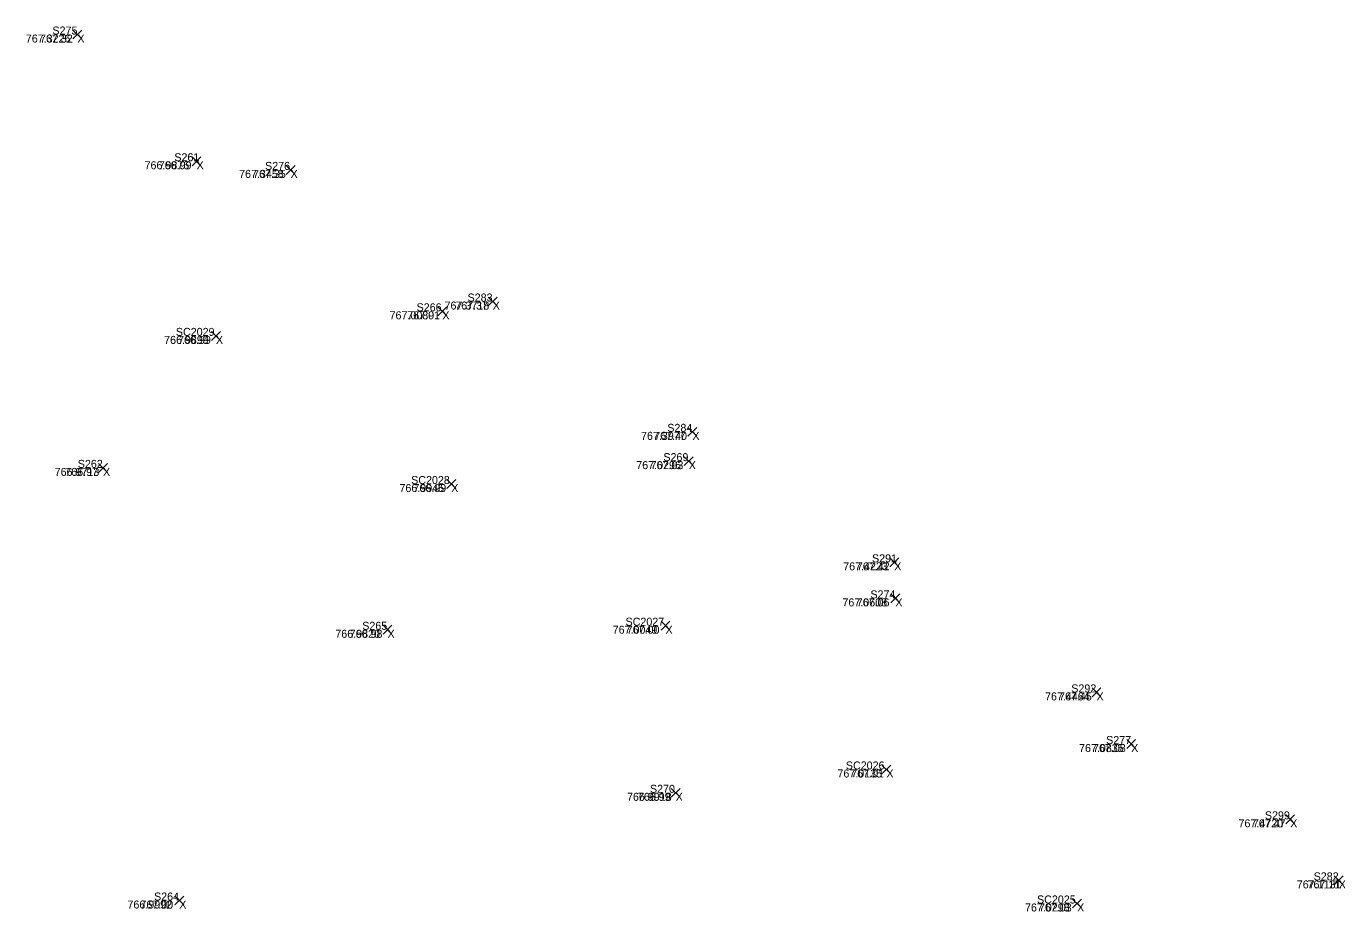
# Model space of a CAD drawing. Extents: x 1845019 to 1877956, y 680444 to 701081.
# Drawn here: x 1857647.67 to 1857657.56, y 694303.02 to 694309.65 of the extents above; entities that cross this region are included whole.
import ezdxf

# ---------------------------------------------------------------- set-up
doc = ezdxf.new("R2010")
doc.units = 0
for name, color, linetype in [('SV_X_Random_Point', 7, 'Continuous'), ('SV_X_Text_Comment', 7, 'Continuous'), ('SV_X_Text_Elevation', 7, 'Continuous'), ('SV_X_Text_Name', 7, 'Continuous')]:
    doc.layers.add(name, color=color, linetype=linetype)

msp = doc.modelspace()

# ---------------------------------------------------------------- linework, layer by layer
at = {"layer": 'SV_X_Random_Point'}
for p, q in [((1857648.0198, 694309.5546), (1857648.0864, 694309.6214)), ((1857648.0198, 694309.6214), (1857648.0864, 694309.5546)), ((1857648.0198, 694309.5546), (1857648.0864, 694309.6214)), ((1857648.0198, 694309.6214), (1857648.0864, 694309.5546)), ((1857648.9129, 694308.6049), (1857648.9795, 694308.6717)), ((1857648.9129, 694308.6717), (1857648.9795, 694308.6049)), ((1857648.9129, 694308.6049), (1857648.9795, 694308.6717)), ((1857648.9129, 694308.6717), (1857648.9795, 694308.6049)), ((1857649.6178, 694308.5401), (1857649.6844, 694308.6069)), ((1857649.6178, 694308.6069), (1857649.6844, 694308.5401)), ((1857649.6178, 694308.5401), (1857649.6844, 694308.6069)), ((1857649.6178, 694308.6069), (1857649.6844, 694308.5401)), ((1857651.1333, 694307.5537), (1857651.1999, 694307.6205)), ((1857651.1333, 694307.6205), (1857651.1999, 694307.5537)), ((1857651.1333, 694307.5537), (1857651.1999, 694307.6205)), ((1857651.1333, 694307.6205), (1857651.1999, 694307.5537)), ((1857650.7559, 694307.4806), (1857650.8225, 694307.5474)), ((1857650.7559, 694307.5474), (1857650.8225, 694307.4806)), ((1857650.7559, 694307.4806), (1857650.8225, 694307.5474)), ((1857650.7559, 694307.5474), (1857650.8225, 694307.4806)), ((1857649.0582, 694307.2962), (1857649.1248, 694307.363)), ((1857649.0582, 694307.363), (1857649.1248, 694307.2962)), ((1857649.0582, 694307.2962), (1857649.1248, 694307.363)), ((1857649.0582, 694307.363), (1857649.1248, 694307.2962)), ((1857652.6304, 694306.5771), (1857652.697, 694306.6439)), ((1857652.6304, 694306.6439), (1857652.697, 694306.5771)), ((1857652.6304, 694306.5771), (1857652.697, 694306.6439)), ((1857652.6304, 694306.6439), (1857652.697, 694306.5771)), ((1857652.603, 694306.3577), (1857652.6696, 694306.4245)), ((1857652.603, 694306.4245), (1857652.6696, 694306.3577)), ((1857652.603, 694306.3577), (1857652.6696, 694306.4245)), ((1857652.603, 694306.4245), (1857652.6696, 694306.3577)), ((1857648.2114, 694306.307), (1857648.278, 694306.3738)), ((1857648.2114, 694306.3738), (1857648.278, 694306.307)), ((1857648.2114, 694306.307), (1857648.278, 694306.3738)), ((1857648.2114, 694306.3738), (1857648.278, 694306.307)), ((1857650.8224, 694306.1861), (1857650.889, 694306.2529)), ((1857650.8224, 694306.2529), (1857650.889, 694306.1861)), ((1857650.8224, 694306.1861), (1857650.889, 694306.2529)), ((1857650.8224, 694306.2529), (1857650.889, 694306.1861)), ((1857654.1438, 694305.5993), (1857654.2104, 694305.6661)), ((1857654.1438, 694305.6661), (1857654.2104, 694305.5993)), ((1857654.1438, 694305.5993), (1857654.2104, 694305.6661)), ((1857654.1438, 694305.6661), (1857654.2104, 694305.5993)), ((1857654.1522, 694305.3292), (1857654.2188, 694305.396)), ((1857654.1522, 694305.396), (1857654.2188, 694305.3292)), ((1857654.1522, 694305.3292), (1857654.2188, 694305.396)), ((1857654.1522, 694305.396), (1857654.2188, 694305.3292)), ((1857650.3445, 694305.0939), (1857650.4111, 694305.1607)), ((1857650.3445, 694305.1607), (1857650.4111, 694305.0939)), ((1857650.3445, 694305.0939), (1857650.4111, 694305.1607)), ((1857650.3445, 694305.1607), (1857650.4111, 694305.0939)), ((1857652.4292, 694305.1244), (1857652.4958, 694305.1912)), ((1857652.4292, 694305.1912), (1857652.4958, 694305.1244)), ((1857652.4292, 694305.1244), (1857652.4958, 694305.1912)), ((1857652.4292, 694305.1912), (1857652.4958, 694305.1244)), ((1857655.6602, 694304.6246), (1857655.7268, 694304.6914)), ((1857655.6602, 694304.6914), (1857655.7268, 694304.6246)), ((1857655.6602, 694304.6246), (1857655.7268, 694304.6914)), ((1857655.6602, 694304.6914), (1857655.7268, 694304.6246)), ((1857655.9203, 694304.2376), (1857655.9869, 694304.3044)), ((1857655.9203, 694304.3044), (1857655.9869, 694304.2376)), ((1857655.9203, 694304.2376), (1857655.9869, 694304.3044)), ((1857655.9203, 694304.3044), (1857655.9869, 694304.2376)), ((1857654.0848, 694304.0472), (1857654.1514, 694304.114)), ((1857654.0848, 694304.114), (1857654.1514, 694304.0472)), ((1857654.0848, 694304.0472), (1857654.1514, 694304.114)), ((1857654.0848, 694304.114), (1857654.1514, 694304.0472)), ((1857652.505, 694303.8722), (1857652.5716, 694303.939)), ((1857652.505, 694303.939), (1857652.5716, 694303.8722)), ((1857652.505, 694303.8722), (1857652.5716, 694303.939)), ((1857652.505, 694303.939), (1857652.5716, 694303.8722)), ((1857657.1128, 694303.6733), (1857657.1794, 694303.7401)), ((1857657.1128, 694303.7401), (1857657.1794, 694303.6733)), ((1857657.1128, 694303.6733), (1857657.1794, 694303.7401)), ((1857657.1128, 694303.7401), (1857657.1794, 694303.6733)), ((1857657.4763, 694303.2159), (1857657.5429, 694303.2827)), ((1857657.4763, 694303.2827), (1857657.5429, 694303.2159)), ((1857657.4763, 694303.2159), (1857657.5429, 694303.2827)), ((1857657.4763, 694303.2827), (1857657.5429, 694303.2159)), ((1857648.7831, 694303.065), (1857648.8497, 694303.1318)), ((1857648.7831, 694303.1318), (1857648.8497, 694303.065)), ((1857648.7831, 694303.065), (1857648.8497, 694303.1318)), ((1857648.7831, 694303.1318), (1857648.8497, 694303.065)), ((1857655.5145, 694303.0429), (1857655.5811, 694303.1097)), ((1857655.5145, 694303.1097), (1857655.5811, 694303.0429)), ((1857655.5145, 694303.0429), (1857655.5811, 694303.1097)), ((1857655.5145, 694303.1097), (1857655.5811, 694303.0429))]:
    msp.add_line(p, q, dxfattribs=at)

# ---------------------------------------------------------------- texts
at = {"layer": 'SV_X_Text_Comment'}
for p in [(1857648.0531, 694309.528), (1857648.9462, 694308.5783), (1857649.6511, 694308.5135), (1857650.7892, 694307.454), (1857651.1666, 694307.5271), (1857649.0915, 694307.2696), (1857652.6637, 694306.5505), (1857648.2447, 694306.2804), (1857652.6363, 694306.3311), (1857650.8557, 694306.1595), (1857654.1771, 694305.5727), (1857654.1855, 694305.3026), (1857650.3778, 694305.0673), (1857652.4625, 694305.0978), (1857655.6935, 694304.598), (1857655.9536, 694304.211), (1857654.1181, 694304.0206), (1857652.5383, 694303.8456), (1857657.1461, 694303.6467), (1857657.5096, 694303.1893), (1857648.8164, 694303.0384), (1857655.5478, 694303.0163)]:
    msp.add_text('X', height=0.06, dxfattribs=at).set_placement(p)
at = {"layer": 'SV_X_Text_Elevation'}
for s, p in [('767.3226', (1857647.6662, 694309.528)), ('767.32', (1857647.7725, 694309.528)), ('766.9876', (1857648.5565, 694308.5783)), ('766.99', (1857648.6628, 694308.5783)), ('767.3458', (1857649.2651, 694308.5135)), ('767.35', (1857649.37, 694308.5135)), ('767.0089', (1857650.3933, 694307.454)), ('767.01', (1857650.526, 694307.454)), ('767.3718', (1857650.8057, 694307.5271)), ('767.37', (1857650.8855, 694307.5271)), ('766.9899', (1857648.7032, 694307.2696)), ('766.99', (1857648.8081, 694307.2696)), ('767.3977', (1857652.2787, 694306.5505)), ('767.40', (1857652.3779, 694306.5505)), ('766.9713', (1857647.8824, 694306.2804)), ('766.97', (1857647.9617, 694306.2804)), ('767.0296', (1857652.2428, 694306.3311)), ('767.03', (1857652.3505, 694306.3311)), ('766.9945', (1857650.4674, 694306.1595)), ('766.99', (1857650.5723, 694306.1595)), ('767.4223', (1857653.7945, 694305.5727)), ('767.42', (1857653.897, 694305.5727)), ('767.0608', (1857653.7887, 694305.3026)), ('767.06', (1857653.8959, 694305.3026)), ('766.9820', (1857649.9866, 694305.0673)), ('766.98', (1857650.0944, 694305.0673)), ('767.0049', (1857652.0661, 694305.0978)), ('767.00', (1857652.1715, 694305.0978)), ('767.4464', (1857655.308, 694304.598)), ('767.45', (1857655.4129, 694304.598)), ('767.0835', (1857655.5629, 694304.211)), ('767.08', (1857655.6673, 694304.211)), ('767.0135', (1857653.7511, 694304.0206)), ('767.01', (1857653.8549, 694304.0206)), ('766.9918', (1857652.1736, 694303.8456)), ('766.99', (1857652.2549, 694303.8456)), ('767.4720', (1857656.7583, 694303.6467)), ('767.47', (1857656.8655, 694303.6467)), ('767.1131', (1857657.1954, 694303.1893)), ('767.11', (1857657.2757, 694303.1893)), ('766.9992', (1857648.4281, 694303.0384)), ('767.00', (1857648.5254, 694303.0384)), ('767.0298', (1857655.1576, 694303.0163)), ('767.03', (1857655.262, 694303.0163))]:
    msp.add_text(s, height=0.06, dxfattribs=at).set_placement(p)
at = {"layer": 'SV_X_Text_Name'}
for s, p in [('S275', (1857647.8656, 694309.588)), ('S275', (1857647.8656, 694309.588)), ('S261', (1857648.7793, 694308.6383)), ('S261', (1857648.7802, 694308.6383)), ('S276', (1857649.4598, 694308.5735)), ('S276', (1857649.4598, 694308.5735)), ('S283', (1857650.9781, 694307.5871)), ('S283', (1857650.9781, 694307.5871)), ('S266', (1857650.596, 694307.514)), ('S266', (1857650.596, 694307.514)), ('SC2029', (1857648.791, 694307.3296)), ('SC2029', (1857648.791, 694307.3296)), ('S284', (1857652.4757, 694306.6105)), ('S284', (1857652.4757, 694306.6105)), ('S269', (1857652.4464, 694306.3911)), ('S269', (1857652.4464, 694306.3911)), ('S262', (1857648.0557, 694306.3404)), ('S262', (1857648.0557, 694306.3404)), ('SC2028', (1857650.5552, 694306.2195)), ('SC2028', (1857650.5552, 694306.2195)), ('S291', (1857654.0102, 694305.6327)), ('S291', (1857654.0111, 694305.6327)), ('S274', (1857653.9984, 694305.3626)), ('S274', (1857653.9984, 694305.3626)), ('S265', (1857650.1884, 694305.1273)), ('S265', (1857650.1884, 694305.1273)), ('SC2027', (1857652.1625, 694305.1578)), ('SC2027', (1857652.1625, 694305.1578)), ('S292', (1857655.5045, 694304.658)), ('S292', (1857655.5045, 694304.658)), ('S277', (1857655.7661, 694304.271)), ('S277', (1857655.7661, 694304.271)), ('SC2026', (1857653.8143, 694304.0806)), ('SC2026', (1857653.8143, 694304.0806)), ('S270', (1857652.3456, 694303.9056)), ('S270', (1857652.3456, 694303.9056)), ('S299', (1857656.9562, 694303.7067)), ('S299', (1857656.9562, 694303.7067)), ('S282', (1857657.3216, 694303.2493)), ('S282', (1857657.3216, 694303.2493)), ('S264', (1857648.6274, 694303.0984)), ('S264', (1857648.6274, 694303.0984)), ('SC2025', (1857655.2478, 694303.0763)), ('SC2025', (1857655.2478, 694303.0763))]:
    msp.add_text(s, height=0.06, dxfattribs=at).set_placement(p)

doc.saveas('drawing.dxf')
